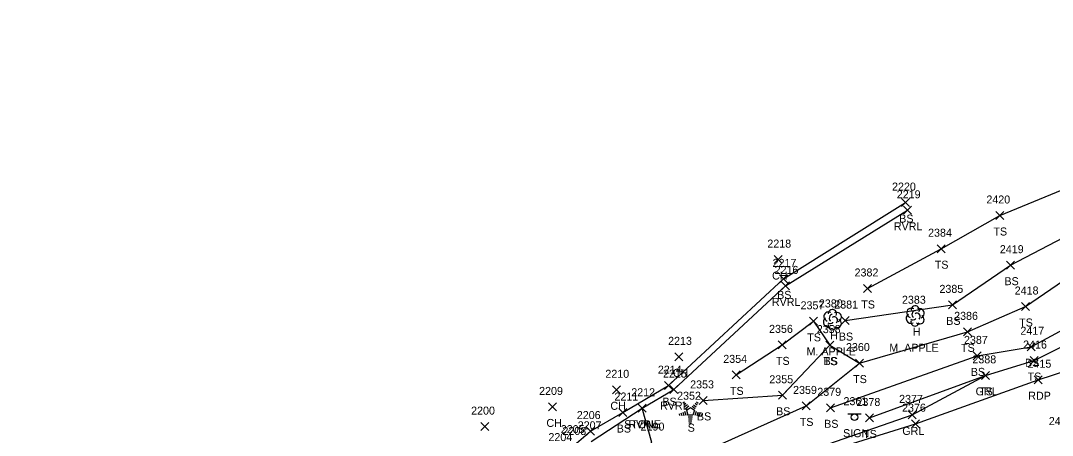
# Model space of a CAD drawing. Extents: x 1699408 to 1700423, y 840176 to 841410.
# Drawn here: x 1699767.4 to 1700025.1, y 840382.8 to 840486.5 of the extents above; entities that cross this region are included whole.
import ezdxf

# ---------------------------------------------------------------- set-up
doc = ezdxf.new("R2010")
doc.units = 0
for name, color, linetype in [('D_I', 7, 'Continuous'), ('L_A', 7, 'Continuous'), ('L_C', 7, 'Continuous'), ('L_I', 7, 'Continuous'), ('L_TIC', 7, 'Continuous'), ('LASF', 7, 'Continuous'), ('LAWE', 7, 'Continuous'), ('LELB', 7, 'Continuous'), ('LTC', 7, 'Continuous'), ('LTD', 7, 'Continuous'), ('P_A', 7, 'Continuous'), ('P_I', 7, 'Continuous'), ('P_TIC', 7, 'Continuous'), ('PET', 7, 'Continuous'), ('R_A', 7, 'Continuous'), ('R_I', 7, 'Continuous'), ('R_TIC', 7, 'Continuous'), ('RGR', 7, 'Continuous'), ('S_A', 7, 'Continuous'), ('S_I', 7, 'Continuous'), ('SSGN', 7, 'Continuous')]:
    doc.layers.add(name, color=color, linetype=linetype)

msp = doc.modelspace()

# ---------------------------------------------------------------- linework, layer by layer
at = {"layer": 'L_TIC'}
for points in [[(1699987.44, 840439.99), (1699989.44, 840441.99)], [(1699989.44, 840439.99), (1699987.44, 840441.99)], [(1699987.97, 840438.06), (1699989.97, 840440.06)], [(1699989.97, 840438.06), (1699987.97, 840440.06)], [(1700011, 840436.76), (1700013, 840438.76)], [(1700013, 840436.76), (1700011, 840438.76)], [(1699996.35, 840428.46), (1699998.35, 840430.46)], [(1699998.35, 840428.46), (1699996.35, 840430.46)], [(1699955.64, 840425.74), (1699957.64, 840427.74)], [(1699957.64, 840425.74), (1699955.64, 840427.74)], [(1700013.72, 840424.34), (1700015.72, 840426.34)], [(1700015.72, 840424.34), (1700013.72, 840426.34)], [(1699956.95, 840420.92), (1699958.95, 840422.92)], [(1699958.95, 840420.92), (1699956.95, 840422.92)], [(1699957.5, 840419.16), (1699959.5, 840421.16)], [(1699959.5, 840419.16), (1699957.5, 840421.16)], [(1699977.99, 840418.52), (1699979.99, 840420.52)], [(1699979.99, 840418.52), (1699977.99, 840420.52)], [(1699999.19, 840414.42), (1700001.19, 840416.42)], [(1700001.19, 840414.42), (1699999.19, 840416.42)], [(1700017.42, 840414.01), (1700019.42, 840416.01)], [(1700019.42, 840414.01), (1700017.42, 840416.01)], [(1699964.5, 840410.31), (1699966.5, 840412.31)], [(1699966.5, 840410.31), (1699964.5, 840412.31)], [(1699972.36, 840410.5), (1699974.36, 840412.5)], [(1699974.36, 840410.5), (1699972.36, 840412.5)], [(1700002.92, 840407.68), (1700004.92, 840409.68)], [(1700004.92, 840407.68), (1700002.92, 840409.68)], [(1699956.68, 840404.42), (1699958.68, 840406.42)], [(1699958.68, 840404.42), (1699956.68, 840406.42)], [(1699968.56, 840404.36), (1699970.56, 840406.36)], [(1699970.56, 840404.36), (1699968.56, 840406.36)], [(1699968.56, 840404.36), (1699970.56, 840406.36)], [(1699970.56, 840404.36), (1699968.56, 840406.36)], [(1700018.85, 840403.95), (1700020.85, 840405.95)], [(1700020.85, 840403.95), (1700018.85, 840405.95)], [(1699930.84, 840401.43), (1699932.84, 840403.43)], [(1699932.84, 840401.43), (1699930.84, 840403.43)], [(1699975.97, 840399.87), (1699977.97, 840401.87)], [(1699977.97, 840399.87), (1699975.97, 840401.87)], [(1699975.97, 840399.87), (1699977.97, 840401.87)], [(1699977.97, 840399.87), (1699975.97, 840401.87)], [(1700005.32, 840401.67), (1700007.32, 840403.67)], [(1700007.32, 840401.67), (1700005.32, 840403.67)], [(1700019.57, 840400.5), (1700021.57, 840402.5)], [(1700021.57, 840400.5), (1700019.57, 840402.5)], [(1699945.19, 840396.92), (1699947.19, 840398.92)], [(1699947.19, 840396.92), (1699945.19, 840398.92)], [(1700007.42, 840396.8), (1700009.42, 840398.8)], [(1700009.42, 840396.8), (1700007.42, 840398.8)], [(1699915.25, 840393.19), (1699917.25, 840395.19)], [(1699917.25, 840393.19), (1699915.25, 840395.19)], [(1699928.29, 840394.23), (1699930.29, 840396.23)], [(1699930.29, 840394.23), (1699928.29, 840396.23)], [(1699929.57, 840393.24), (1699931.57, 840395.24)], [(1699931.57, 840393.24), (1699929.57, 840395.24)], [(1699936.92, 840390.54), (1699938.92, 840392.54)], [(1699938.92, 840390.54), (1699936.92, 840392.54)], [(1699956.69, 840391.82), (1699958.69, 840393.82)], [(1699958.69, 840391.82), (1699956.69, 840393.82)], [(1699899.27, 840388.91), (1699901.27, 840390.91)], [(1699901.27, 840388.91), (1699899.27, 840390.91)], [(1699916.88, 840387.51), (1699918.88, 840389.51)], [(1699918.88, 840387.51), (1699916.88, 840389.51)], [(1699921.64, 840388.58), (1699923.64, 840390.58)], [(1699923.64, 840388.58), (1699921.64, 840390.58)], [(1699921.64, 840388.58), (1699923.64, 840390.58)], [(1699923.64, 840388.58), (1699921.64, 840390.58)], [(1699962.63, 840389.16), (1699964.63, 840391.16)], [(1699964.63, 840389.16), (1699962.63, 840391.16)], [(1699968.68, 840388.69), (1699970.68, 840390.69)], [(1699970.68, 840388.69), (1699968.68, 840390.69)], [(1699978.47, 840386.15), (1699980.47, 840388.15)], [(1699980.47, 840386.15), (1699978.47, 840388.15)], [(1699882.38, 840383.99), (1699884.38, 840385.99)], [(1699884.38, 840383.99), (1699882.38, 840385.99)], [(1699908.75, 840382.88), (1699910.75, 840384.88)], [(1699910.75, 840382.88), (1699908.75, 840384.88)]]:
    msp.add_lwpolyline(points, dxfattribs=at)
at = {"layer": 'LASF'}
msp.add_lwpolyline([(1699851.14, 840356.43), (1699867.77, 840361.02), (1699888.01, 840366.67), (1699907.74, 840370.19), (1699925.07, 840381), (1699922.64, 840389.58)], dxfattribs=at)
at = {"layer": 'LAWE'}
msp.add_lwpolyline([(1699909.92, 840381.31), (1699922.64, 840389.58), (1699930.57, 840394.24), (1699958.5, 840420.16), (1699988.97, 840439.06)], dxfattribs=at)
at = {"layer": 'LELB'}
for points in [[(1699978.99, 840419.52), (1699997.35, 840429.46), (1700012, 840437.76), (1700038.88, 840448.85), (1700052.08, 840456.47), (1700082.74, 840486.47)], [(1699973.36, 840411.5), (1700000.19, 840415.42), (1700014.72, 840425.34), (1700043.23, 840440.25), (1700050.16, 840438.65), (1700060.22, 840450.07), (1700081.83, 840471.38), (1700087.48, 840483.44)], [(1699979.47, 840387.15), (1700008.42, 840397.8), (1700020.57, 840401.5), (1700064.16, 840423.4), (1700071.23, 840436.53), (1700084.61, 840449.01), (1700098.79, 840471.3), (1700102.69, 840480.98)], [(1699782.01, 840352.31), (1699821.1, 840358.64), (1699847.49, 840362.44), (1699872, 840367.97), (1699887.26, 840376.59), (1699902.6, 840378.37), (1699905.68, 840380.36), (1699909.75, 840383.88), (1699917.88, 840388.51), (1699929.29, 840395.23), (1699957.95, 840421.92), (1699988.44, 840440.99)], [(1699946.19, 840397.92), (1699957.68, 840405.42), (1699965.5, 840411.31), (1699969.56, 840405.36), (1699976.97, 840400.87), (1700003.92, 840408.68), (1700018.42, 840415.01), (1700043.97, 840432.54), (1700060.87, 840436.32)], [(1699969.68, 840389.69), (1700006.32, 840402.67), (1700019.85, 840404.95), (1700061.26, 840427.31)], [(1699937.92, 840391.54), (1699957.69, 840392.82), (1699969.56, 840405.36)], [(1699784.06, 840343.1), (1699812.78, 840343), (1699846.79, 840350.66), (1699873.28, 840357.14), (1699911.79, 840368.31), (1699928.14, 840374.26), (1699963.63, 840390.16), (1699976.97, 840400.87)]]:
    msp.add_lwpolyline(points, dxfattribs=at)
at = {"layer": 'LTC'}
for p, q in [((1699932.85, 840390.92), (1699933.21, 840391.17)), ((1699933.06, 840390.45), (1699933.59, 840390.83)), ((1699933.27, 840389.98), (1699933.98, 840390.5)), ((1699933.48, 840389.52), (1699934.36, 840390.16)), ((1699933.71, 840389.06), (1699934.72, 840389.8)), ((1699933.71, 840389.06), (1699934.09, 840387.87)), ((1699934.72, 840389.8), (1699935.71, 840389.07)), ((1699935.14, 840390.11), (1699935.95, 840389.52)), ((1699935.71, 840389.07), (1699935.32, 840387.87)), ((1699935.51, 840390.46), (1699936.19, 840389.97)), ((1699935.88, 840390.81), (1699936.43, 840390.41)), ((1699936.25, 840391.16), (1699936.67, 840390.85)), ((1699931.88, 840388.2), (1699932.04, 840387.73)), ((1699932.34, 840388.41), (1699932.55, 840387.76)), ((1699932.8, 840388.63), (1699933.07, 840387.79)), ((1699933.25, 840388.84), (1699933.58, 840387.83)), ((1699935.32, 840387.87), (1699934.09, 840387.87)), ((1699935.28, 840387.37), (1699934.14, 840387.37)), ((1699935.2, 840386.87), (1699934.21, 840386.87)), ((1699935.12, 840386.37), (1699934.29, 840386.37)), ((1699936.15, 840388.8), (1699935.81, 840387.76)), ((1699936.6, 840388.55), (1699936.31, 840387.67)), ((1699937.04, 840388.3), (1699936.8, 840387.57)), ((1699937.49, 840388.05), (1699937.3, 840387.48)), ((1699935.03, 840385.87), (1699934.36, 840385.87))]:
    msp.add_line(p, q, dxfattribs=at)
at = {"layer": 'LTD'}
for p, q in [((1699990.83, 840412.7), (1699990.83, 840412.7)), ((1699990.83, 840412.7), (1699990.83, 840412.7)), ((1699970.16, 840411.78), (1699970.16, 840411.78)), ((1699970.16, 840411.78), (1699970.16, 840411.78))]:
    msp.add_line(p, q, dxfattribs=at)
for centre in [(1699990.88, 840414.14), (1699970.21, 840413.21)]:
    msp.add_arc(centre, 1.05, 335.5272, 180.9563, dxfattribs=at)
for centre, major_axis, ratio, start_param, end_param in [((1699990.04, 840413.37), (1.21, -0.51), 0.895232, 1.570796, 4.712389), ((1699969.08, 840411.07), (0.58, -1.04), 0.959034, 3.141593, 6.283185), ((1699969.37, 840412.44), (1.21, -0.51), 0.895232, 1.570796, 4.712389), ((1699969.96, 840412.23), (-0.208, -0.792), 0.645439, 3.141593, 6.283185), ((1699970.66, 840411.61), (-0.5, 0.667), 0.989748, 3.141593, 6.283185), ((1699971.21, 840412.36), (-1.14, -0.48), 0.949671, 1.570796, 4.712389), ((1699989.75, 840412), (0.58, -1.04), 0.959034, 3.141593, 6.283185), ((1699990.62, 840413.16), (-0.208, -0.792), 0.645439, 3.141593, 6.283185), ((1699991.33, 840412.54), (-0.5, 0.667), 0.989748, 3.141593, 6.283185), ((1699991.83, 840411.87), (-1.09, 0.79), 0.841452, 1.570796, 4.712389), ((1699991.87, 840413.29), (-1.14, -0.48), 0.949671, 1.570796, 4.712389), ((1699970.16, 840410.28), (0.26, 1.06), 0.942809, 1.570796, 4.712389), ((1699969.71, 840411.03), (-0.625, -0.083), 0.423636, 0, 3.141593), ((1699971.16, 840410.94), (-1.09, 0.79), 0.841452, 1.570796, 4.712389), ((1699990.83, 840411.2), (0.26, 1.06), 0.942809, 1.570796, 4.712389), ((1699990.37, 840411.95), (-0.625, -0.083), 0.423636, 0, 3.141593)]:
    msp.add_ellipse(centre, major_axis=major_axis, ratio=ratio, start_param=start_param, end_param=end_param, dxfattribs=at)
at = {"layer": 'P_TIC'}
for points in [[(1700020.62, 840395.71), (1700022.62, 840397.71)], [(1700022.62, 840395.71), (1700020.62, 840397.71)], [(1699989.91, 840384.72), (1699991.91, 840386.72)], [(1699991.91, 840384.72), (1699989.91, 840386.72)]]:
    msp.add_lwpolyline(points, dxfattribs=at)
at = {"layer": 'PET'}
msp.add_lwpolyline([(1699430.72, 840228.22), (1699466.92, 840252.65), (1699493.58, 840268.87), (1699501.63, 840273.58), (1699505.33, 840277.49), (1699516.37, 840283.58), (1699542.26, 840294.23), (1699569.87, 840304.55), (1699598.29, 840312.45), (1699620.64, 840316.32), (1699670.9, 840322.33), (1699702.16, 840325.07), (1699741.15, 840329.16), (1699780.55, 840332.75), (1699814.05, 840338.23), (1699848.8, 840345.35), (1699873.3, 840351.35), (1699914.22, 840362.32), (1699930.57, 840367.02), (1699959.45, 840375.82), (1699990.91, 840385.72), (1700021.62, 840396.71), (1700043.81, 840403.93)], dxfattribs=at)
at = {"layer": 'R_TIC'}
for points in [[(1700007.42, 840396.8), (1700009.42, 840398.8)], [(1700009.42, 840396.8), (1700007.42, 840398.8)], [(1699989.11, 840386.92), (1699991.11, 840388.92)], [(1699991.11, 840386.92), (1699989.11, 840388.92)]]:
    msp.add_lwpolyline(points, dxfattribs=at)
at = {"layer": 'RGR'}
msp.add_lwpolyline([(1699728.48, 840335.43), (1699752.54, 840332.39), (1699780.34, 840334.41), (1699813.44, 840339.9), (1699849.41, 840347.4), (1699873.97, 840353.47), (1699916.95, 840364.91), (1699929.95, 840368.59), (1699959.73, 840377.35), (1699990.11, 840387.92), (1700008.42, 840397.8)], dxfattribs=at)
at = {"layer": 'SSGN'}
for p, q in [((1699974.07, 840388.21), (1699977.41, 840388.21)), ((1699975.72, 840387.37), (1699975.72, 840387.37))]:
    msp.add_line(p, q, dxfattribs=at)
msp.add_circle((1699975.72, 840387.37), 0.833, dxfattribs=at)

# ---------------------------------------------------------------- texts
at = {"layer": 'D_I'}
msp.add_text('2208', height=2, dxfattribs=at).set_placement((1699902.76, 840382.9))
at = {"layer": 'L_A'}
for s, p in [('BS', (1699986.88, 840435.99)), ('RVRL', (1699985.54, 840434.06)), ('TS', (1700010.41, 840432.76)), ('TS', (1699995.76, 840424.46)), ('CH', (1699955.12, 840421.74)), ('BS', (1700013.16, 840420.34)), ('BS', (1699956.39, 840416.92)), ('RVRL', (1699955.07, 840415.16)), ('TS', (1699977.4, 840414.52)), ('BS', (1699998.63, 840410.42)), ('H', (1699990.26, 840407.7)), ('TS', (1700016.83, 840410.01)), ('TS', (1699963.91, 840406.31)), ('H', (1699969.6, 840406.78)), ('BS', (1699971.8, 840406.5)), ('TS', (1700002.33, 840403.68)), ('TS', (1699956.09, 840400.42)), ('TS', (1699967.97, 840400.36)), ('BS', (1699968, 840400.36)), ('BS', (1700018.29, 840399.95)), ('CH', (1699930.33, 840397.43)), ('BS', (1700004.76, 840397.67)), ('TS', (1699975.38, 840395.87)), ('TS', (1699975.38, 840395.87)), ('TS', (1700018.98, 840396.5)), ('TS', (1699944.6, 840392.92)), ('TS', (1700006.83, 840392.8)), ('BS', (1699927.73, 840390.23)), ('CH', (1699914.74, 840389.19)), ('RVRL', (1699927.14, 840389.24)), ('BS', (1699956.13, 840387.82)), ('CH', (1699898.76, 840384.91)), ('STONE', (1699918.19, 840384.58)), ('RVRL', (1699919.21, 840384.58)), ('BS', (1699936.36, 840386.54)), ('TS', (1699962.04, 840385.16)), ('BS', (1699968.13, 840384.69)), ('BS', (1699916.32, 840383.51)), ('S', (1699934.04, 840383.71)), ('TS', (1699977.88, 840382.15))]:
    msp.add_text(s, height=2, dxfattribs=at).set_placement(p)
at = {"layer": 'L_C'}
for p in [(1699963.74, 840402.78), (1699984.41, 840403.7)]:
    msp.add_text('M. APPLE', height=2, dxfattribs=at).set_placement(p)
at = {"layer": 'L_I'}
for s, p in [('2220', (1699985.09, 840443.99)), ('2219', (1699986.27, 840442.06)), ('2420', (1700008.65, 840440.76)), ('2384', (1699994.09, 840432.46)), ('2218', (1699953.94, 840429.74)), ('2419', (1700012.02, 840428.34)), ('2217', (1699955.26, 840424.92)), ('2216', (1699955.76, 840423.16)), ('2382', (1699975.73, 840422.52)), ('2385', (1699996.93, 840418.42)), ('2418', (1700015.73, 840418.01)), ('2383', (1699987.57, 840415.7)), ('2357', (1699962.24, 840414.31)), ('2380', (1699966.82, 840414.78)), ('2381', (1699970.66, 840414.5)), ('2386', (1700000.6, 840411.68)), ('2356', (1699954.37, 840408.42)), ('2358', (1699966.3, 840408.36)), ('2358', (1699966.3, 840408.36)), ('2417', (1700017.15, 840407.95)), ('2213', (1699929.15, 840405.43)), ('2387', (1700003.06, 840405.67)), ('2360', (1699973.58, 840403.87)), ('2360', (1699973.58, 840403.87)), ('2416', (1700017.83, 840404.5)), ('2354', (1699942.93, 840400.92)), ('2388', (1700005.16, 840400.8)), ('2210', (1699913.48, 840397.19)), ('2214', (1699926.6, 840398.23)), ('2215', (1699927.88, 840397.24)), ('2355', (1699954.43, 840395.82)), ('2209', (1699896.93, 840392.91)), ('2212', (1699919.95, 840392.58)), ('2212', (1699919.95, 840392.58)), ('2353', (1699934.66, 840394.54)), ('2359', (1699960.37, 840393.16)), ('2379', (1699966.42, 840392.69)), ('2211', (1699915.76, 840391.51)), ('2352', (1699931.4, 840391.71)), ('2378', (1699976.21, 840390.15)), ('2200', (1699879.95, 840387.99)), ('2206', (1699906.35, 840386.88)), ('2207', (1699906.58, 840384.31)), ('2205', (1699902.34, 840383.36)), ('2190', (1699922.29, 840384)), ('2204', (1699899.26, 840381.37))]:
    msp.add_text(s, height=2, dxfattribs=at).set_placement(p)
at = {"layer": 'LTC'}
msp.add_text('.', height=1.04, rotation=270, dxfattribs=at).set_placement((1699934.6, 840388.81))
at = {"layer": 'P_A'}
msp.add_text('RDP', height=2, dxfattribs=at).set_placement((1700019.11, 840391.71))
at = {"layer": 'P_I'}
for s, p in [('2415', (1700018.93, 840399.71)), ('2376', (1699987.59, 840388.72)), ('2414', (1700024.25, 840385.38))]:
    msp.add_text(s, height=2, dxfattribs=at).set_placement(p)
at = {"layer": 'R_A'}
for p in [(1700005.96, 840392.8), (1699987.65, 840382.92)]:
    msp.add_text('GRL', height=2, dxfattribs=at).set_placement(p)
at = {"layer": 'R_I'}
for s, p in [('2388', (1700005.16, 840400.8)), ('2377', (1699986.85, 840390.92))]:
    msp.add_text(s, height=2, dxfattribs=at).set_placement(p)
at = {"layer": 'S_A'}
msp.add_text('SIGN', height=2, dxfattribs=at).set_placement((1699972.86, 840382.35))
at = {"layer": 'S_I'}
msp.add_text('2361', height=2, dxfattribs=at).set_placement((1699972.96, 840390.35))

doc.saveas('drawing.dxf')
